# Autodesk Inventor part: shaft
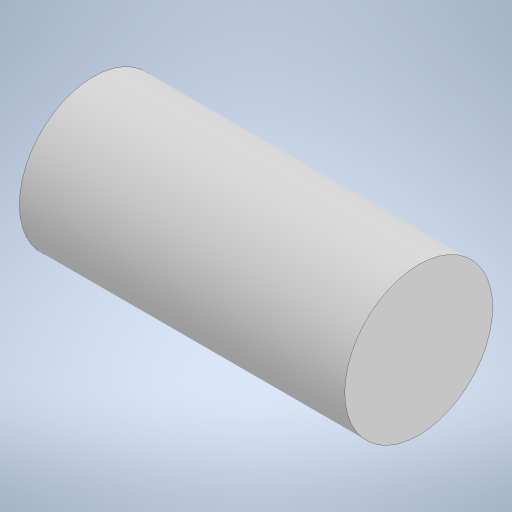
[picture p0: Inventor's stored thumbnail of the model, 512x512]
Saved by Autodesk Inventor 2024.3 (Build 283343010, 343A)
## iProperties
Created: 2025-10
Part Number: shaft
Material: 一般
Document SubType Name: Modeling
Designer: kouki
Density: 1 g/cm^3
Appearance: 既定
Author: kouki
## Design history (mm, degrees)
sketch "スケッチ1"
  geometry: C1 r 2.5 at (0, 0); 1 further point
  constraints: 1 centre point, 1 coincident
  dimensions: "d0" = 5 diameter of C1
extrude "押し出し1" new body sketch "スケッチ1" stored distance "d1" = 11; taper "d2" = 0 deg
node "ソリッド1"
